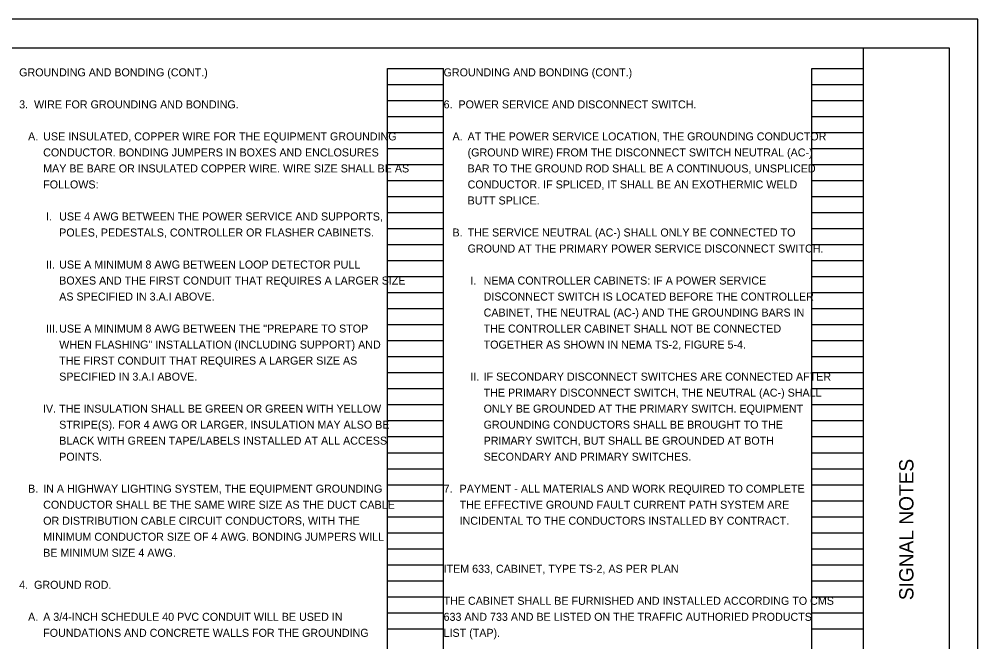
# Model space of a CAD drawing. Extents: x 0 to 34, y 0 to 22.
# Drawn here: x 17.24 to 34, y 11.11 to 22 of the extents above; entities that cross this region are included whole.
import ezdxf

# ---------------------------------------------------------------- set-up
doc = ezdxf.new("R2010")
doc.units = 0
for name, color, linetype in [('SH_Border', 7, 'Continuous'), ('SH_Cut_Line', 7, 'Continuous'), ('SH_Data', 7, 'Continuous'), ('SH_Text', 7, 'Continuous')]:
    doc.layers.add(name, color=color, linetype=linetype)

msp = doc.modelspace()

# ---------------------------------------------------------------- linework, layer by layer
at = {"layer": 'SH_Border'}
msp.add_line((32, 0.5), (32, 21.5), dxfattribs=at)
msp.add_lwpolyline([(1.5, 21.5), (33.5, 21.5), (33.5, 0.5), (1.5, 0.5)], close=True, dxfattribs=at)
at = {"layer": 'SH_Cut_Line'}
msp.add_lwpolyline([(0, 0), (34, 0), (34, 22), (0, 22)], close=True, dxfattribs=at)
at = {"layer": 'SH_Data'}
for p, q in [((23.68, 0.98), (23.68, 21.14)), ((23.68, 21.14), (24.66, 21.14)), ((24.66, 0.98), (24.66, 21.14)), ((31.1, 0.98), (31.1, 21.14)), ((31.1, 21.14), (32, 21.14)), ((32, 0.98), (32, 21.14)), ((23.68, 20.86), (24.66, 20.86)), ((31.1, 20.86), (32, 20.86)), ((23.68, 20.58), (24.66, 20.58)), ((31.1, 20.58), (32, 20.58)), ((23.68, 20.3), (24.66, 20.3)), ((31.1, 20.3), (32, 20.3)), ((23.68, 20.02), (24.66, 20.02)), ((31.1, 20.02), (32, 20.02)), ((23.68, 19.74), (24.66, 19.74)), ((31.1, 19.74), (32, 19.74)), ((23.68, 19.46), (24.66, 19.46)), ((31.1, 19.46), (32, 19.46)), ((23.68, 19.18), (24.66, 19.18)), ((31.1, 19.18), (32, 19.18)), ((23.68, 18.9), (24.66, 18.9)), ((31.1, 18.9), (32, 18.9)), ((23.68, 18.62), (24.66, 18.62)), ((31.1, 18.62), (32, 18.62)), ((23.68, 18.34), (24.66, 18.34)), ((31.1, 18.34), (32, 18.34)), ((23.68, 18.06), (24.66, 18.06)), ((31.1, 18.06), (32, 18.06)), ((23.68, 17.78), (24.66, 17.78)), ((31.1, 17.78), (32, 17.78)), ((23.68, 17.5), (24.66, 17.5)), ((31.1, 17.5), (32, 17.5)), ((23.68, 17.22), (24.66, 17.22)), ((31.1, 17.22), (32, 17.22)), ((23.68, 16.94), (24.66, 16.94)), ((31.1, 16.94), (32, 16.94)), ((23.68, 16.66), (24.66, 16.66)), ((31.1, 16.66), (32, 16.66)), ((23.68, 16.38), (24.66, 16.38)), ((31.1, 16.38), (32, 16.38)), ((23.68, 16.1), (24.66, 16.1)), ((31.1, 16.1), (32, 16.1)), ((23.68, 15.82), (24.66, 15.82)), ((31.1, 15.82), (32, 15.82)), ((23.68, 15.54), (24.66, 15.54)), ((31.1, 15.54), (32, 15.54)), ((23.68, 15.26), (24.66, 15.26)), ((31.1, 15.26), (32, 15.26)), ((23.68, 14.98), (24.66, 14.98)), ((31.1, 14.98), (32, 14.98)), ((23.68, 14.7), (24.66, 14.7)), ((31.1, 14.7), (32, 14.7)), ((23.68, 14.42), (24.66, 14.42)), ((31.1, 14.42), (32, 14.42)), ((23.68, 14.14), (24.66, 14.14)), ((31.1, 14.14), (32, 14.14)), ((23.68, 13.86), (24.66, 13.86)), ((31.1, 13.86), (32, 13.86)), ((23.68, 13.58), (24.66, 13.58)), ((31.1, 13.58), (32, 13.58)), ((23.68, 13.3), (24.66, 13.3)), ((31.1, 13.3), (32, 13.3)), ((23.68, 13.02), (24.66, 13.02)), ((31.1, 13.02), (32, 13.02)), ((23.68, 12.74), (24.66, 12.74)), ((31.1, 12.74), (32, 12.74)), ((23.68, 12.46), (24.66, 12.46)), ((31.1, 12.46), (32, 12.46)), ((23.68, 12.18), (24.66, 12.18)), ((31.1, 12.18), (32, 12.18)), ((23.68, 11.9), (24.66, 11.9)), ((31.1, 11.9), (32, 11.9)), ((23.68, 11.62), (24.66, 11.62)), ((31.1, 11.62), (32, 11.62)), ((23.68, 11.34), (24.66, 11.34)), ((31.1, 11.34), (32, 11.34))]:
    msp.add_line(p, q, dxfattribs=at)

# ---------------------------------------------------------------- texts
msp.add_text('SIGNAL NOTES', height=0.25, rotation=90, dxfattribs=at).set_placement((32.875, 11.841))
at = {"layer": 'SH_Text'}
for s, p in [('GROUNDING AND BONDING (CONT.)', (17.24, 21)), ('GROUNDING AND BONDING (CONT.)', (24.66, 21)), ('3.  WIRE FOR GROUNDING AND BONDING.', (17.24, 20.44)), ('6.  POWER SERVICE AND DISCONNECT SWITCH.', (24.66, 20.44)), ('   A.', (17.24, 19.88)), ('USE INSULATED, COPPER WIRE FOR THE EQUIPMENT GROUNDING', (17.66, 19.88)), ('   A.', (24.66, 19.88)), ('AT THE POWER SERVICE LOCATION, THE GROUNDING CONDUCTOR ', (25.08, 19.88)), ('CONDUCTOR. BONDING JUMPERS IN BOXES AND ENCLOSURES ', (17.66, 19.6)), ('(GROUND WIRE) FROM THE DISCONNECT SWITCH NEUTRAL (AC-) ', (25.08, 19.6)), ('MAY BE BARE OR INSULATED COPPER WIRE. WIRE SIZE SHALL BE AS ', (17.66, 19.32)), ('BAR TO THE GROUND ROD SHALL BE A CONTINUOUS, UNSPLICED ', (25.08, 19.32)), ('FOLLOWS:', (17.66, 19.04)), ('CONDUCTOR. IF SPLICED, IT SHALL BE AN EXOTHERMIC WELD ', (25.08, 19.04)), ('BUTT SPLICE.', (25.08, 18.76)), ('         I.', (17.24, 18.48)), ('USE 4 AWG BETWEEN THE POWER SERVICE AND SUPPORTS, ', (17.94, 18.48)), ('POLES, PEDESTALS, CONTROLLER OR FLASHER CABINETS.', (17.94, 18.2)), ('   B.', (24.66, 18.2)), ('THE SERVICE NEUTRAL (AC-) SHALL ONLY BE CONNECTED TO ', (25.08, 18.2)), ('GROUND AT THE PRIMARY POWER SERVICE DISCONNECT SWITCH.', (25.08, 17.92)), ('         II.', (17.24, 17.64)), ('USE A MINIMUM 8 AWG BETWEEN LOOP DETECTOR PULL ', (17.94, 17.64)), ('BOXES AND THE FIRST CONDUIT THAT REQUIRES A LARGER SIZE ', (17.94, 17.36)), ('         I.', (24.66, 17.36)), ('NEMA CONTROLLER CABINETS: IF A POWER SERVICE ', (25.36, 17.36)), ('AS SPECIFIED IN 3.A.I ABOVE.', (17.94, 17.08)), ('DISCONNECT SWITCH IS LOCATED BEFORE THE CONTROLLER ', (25.36, 17.08)), ('CABINET, THE NEUTRAL (AC-) AND THE GROUNDING BARS IN ', (25.36, 16.8)), ('         III.', (17.24, 16.52)), ('USE A MINIMUM 8 AWG BETWEEN THE "PREPARE TO STOP ', (17.94, 16.52)), ('THE CONTROLLER CABINET SHALL NOT BE CONNECTED', (25.36, 16.52)), ('WHEN FLASHING" INSTALLATION (INCLUDING SUPPORT) AND ', (17.94, 16.24)), ('TOGETHER AS SHOWN IN NEMA TS-2, FIGURE 5-4.', (25.36, 16.24)), ('THE FIRST CONDUIT THAT REQUIRES A LARGER SIZE AS ', (17.94, 15.96)), ('SPECIFIED IN 3.A.I ABOVE.', (17.94, 15.68)), ('         II.', (24.66, 15.68)), ('IF SECONDARY DISCONNECT SWITCHES ARE CONNECTED AFTER ', (25.36, 15.68)), ('THE PRIMARY DISCONNECT SWITCH, THE NEUTRAL (AC-) SHALL ', (25.36, 15.4)), ('        IV.', (17.24, 15.12)), ('THE INSULATION SHALL BE GREEN OR GREEN WITH YELLOW ', (17.94, 15.12)), ('ONLY BE GROUNDED AT THE PRIMARY SWITCH. EQUIPMENT ', (25.36, 15.12)), ('STRIPE(S). FOR 4 AWG OR LARGER, INSULATION MAY ALSO BE ', (17.94, 14.84)), ('GROUNDING CONDUCTORS SHALL BE BROUGHT TO THE ', (25.36, 14.84)), ('BLACK WITH GREEN TAPE/LABELS INSTALLED AT ALL ACCESS ', (17.94, 14.56)), ('PRIMARY SWITCH, BUT SHALL BE GROUNDED AT BOTH ', (25.36, 14.56)), ('POINTS.', (17.94, 14.28)), ('SECONDARY AND PRIMARY SWITCHES.', (25.36, 14.28)), ('   B.', (17.24, 13.72)), ('IN A HIGHWAY LIGHTING SYSTEM, THE EQUIPMENT GROUNDING ', (17.66, 13.72)), ('7. ', (24.66, 13.72)), ('PAYMENT - ALL MATERIALS AND WORK REQUIRED TO COMPLETE ', (24.94, 13.72)), ('CONDUCTOR SHALL BE THE SAME WIRE SIZE AS THE DUCT CABLE ', (17.66, 13.44)), ('THE EFFECTIVE GROUND FAULT CURRENT PATH SYSTEM ARE ', (24.94, 13.44)), ('OR DISTRIBUTION CABLE CIRCUIT CONDUCTORS, WITH THE ', (17.66, 13.16)), ('INCIDENTAL TO THE CONDUCTORS INSTALLED BY CONTRACT.', (24.94, 13.16)), ('MINIMUM CONDUCTOR SIZE OF 4 AWG. BONDING JUMPERS WILL ', (17.66, 12.88)), ('BE MINIMUM SIZE 4 AWG.', (17.66, 12.6)), ('ITEM 633, CABINET, TYPE TS-2, AS PER PLAN', (24.66, 12.32)), ('4.  GROUND ROD.', (17.24, 12.04)), ('THE CABINET SHALL BE FURNISHED AND INSTALLED ACCORDING TO CMS ', (24.66, 11.76)), ('   A.', (17.24, 11.48)), ('A 3/4-INCH SCHEDULE 40 PVC CONDUIT WILL BE USED IN ', (17.66, 11.48)), ('633 AND 733 AND BE LISTED ON THE TRAFFIC AUTHORIED PRODUCTS ', (24.66, 11.48)), ('FOUNDATIONS AND CONCRETE WALLS FOR THE GROUNDING ', (17.66, 11.2)), ('LIST (TAP).', (24.66, 11.2))]:
    msp.add_text(s, height=0.14, dxfattribs=at).set_placement(p)

doc.saveas('drawing.dxf')
